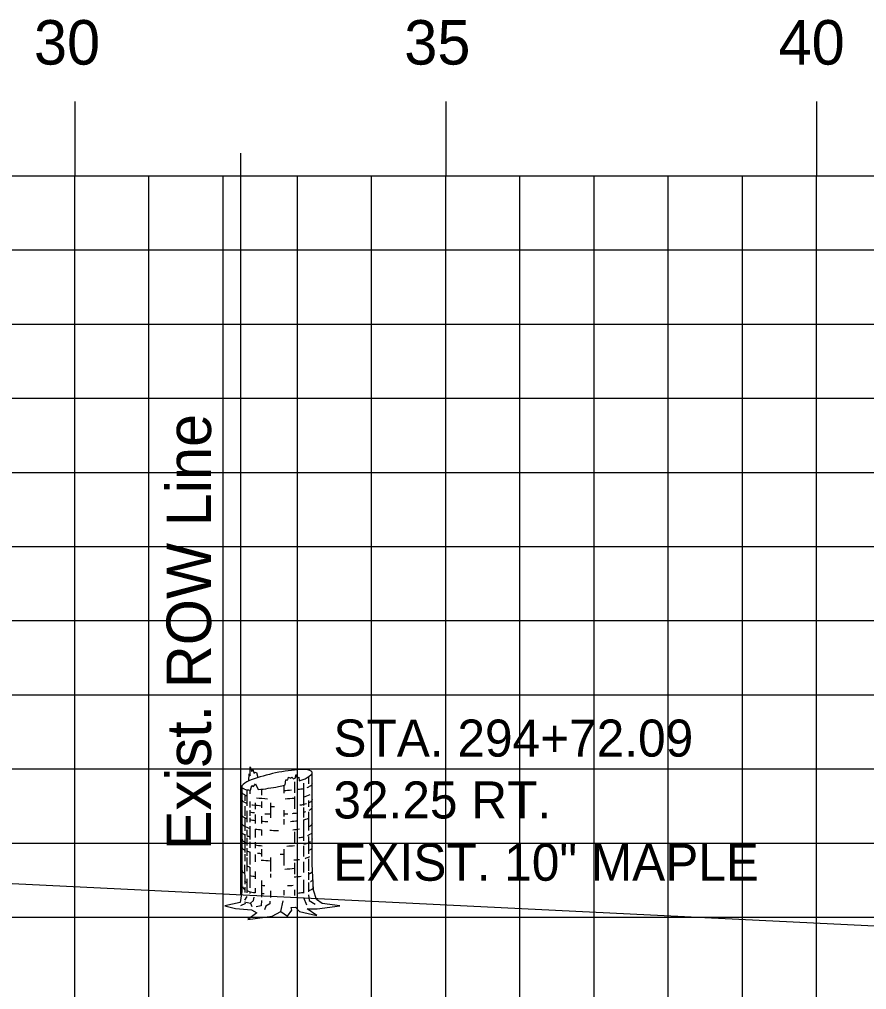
# Model space of a CAD drawing. Extents: x 859352 to 859522, y 366268 to 366378.
# Drawn here: x 859464.38 to 859475.8, y 366316.26 to 366329.35 of the extents above; entities that cross this region are included whole.
import ezdxf

# ---------------------------------------------------------------- set-up
doc = ezdxf.new("R2010")
doc.units = 0
for name, color, linetype in [('D_Text_Monospaced', 7, 'Continuous'), ('E_ROW_Line', 7, 'Continuous'), ('H_V ANNOTATION', 7, 'Continuous'), ('MAJOR', 7, 'Continuous'), ('MINOR', 7, 'Continuous'), ('S_Roadway_Centerline', 7, 'Continuous'), ('S_Trees_Decid_NonPay', 7, 'Continuous')]:
    doc.layers.add(name, color=color, linetype=linetype)

msp = doc.modelspace()

# ---------------------------------------------------------------- linework, layer by layer
at = {"layer": 'E_ROW_Line'}
msp.add_line((859467.365, 366317.54), (859467.365, 366327.54), dxfattribs=at)
at = {"layer": 'MAJOR'}
for p, q in [((859465.129, 366328.238), (859465.129, 366327.236)), ((859470.129, 366328.238), (859470.129, 366327.236)), ((859475.129, 366328.238), (859475.129, 366327.236)), ((859365.129, 366327.236), (859505.129, 366327.236)), ((859365.129, 366327.236), (859505.129, 366327.236)), ((859465.129, 366307.236), (859465.129, 366327.236)), ((859470.129, 366307.236), (859470.129, 366327.236)), ((859475.129, 366307.236), (859475.129, 366327.236)), ((859365.129, 366322.236), (859505.129, 366322.236)), ((859365.129, 366317.236), (859505.129, 366317.236))]:
    msp.add_line(p, q, dxfattribs=at)
at = {"layer": 'MINOR'}
for p, q in [((859466.129, 366307.236), (859466.129, 366327.236)), ((859467.129, 366307.236), (859467.129, 366327.236)), ((859468.129, 366307.236), (859468.129, 366327.236)), ((859469.129, 366307.236), (859469.129, 366327.236)), ((859471.129, 366307.236), (859471.129, 366327.236)), ((859472.129, 366307.236), (859472.129, 366327.236)), ((859473.129, 366307.236), (859473.129, 366327.236)), ((859474.129, 366307.236), (859474.129, 366327.236)), ((859365.129, 366326.236), (859505.129, 366326.236)), ((859365.129, 366325.236), (859505.129, 366325.236)), ((859365.129, 366324.236), (859505.129, 366324.236)), ((859365.129, 366323.236), (859505.129, 366323.236)), ((859365.129, 366321.236), (859505.129, 366321.236)), ((859365.129, 366320.236), (859505.129, 366320.236)), ((859365.129, 366319.236), (859505.129, 366319.236)), ((859365.129, 366318.236), (859505.129, 366318.236))]:
    msp.add_line(p, q, dxfattribs=at)
at = {"layer": 'S_Roadway_Centerline'}
msp.add_lwpolyline([(859412.42, 366318.362), (859414.836, 366318.508), (859414.896, 366318.514), (859415.419, 366318.501), (859418.966, 366318.416), (859419.801, 366318.381), (859419.866, 366318.325), (859420.288, 366317.857), (859421.018, 366317.889), (859421.622, 366317.921), (859424.052, 366318.059), (859425.006, 366318.102), (859426.771, 366318.136), (859435.819, 366318.308), (859444.518, 366318.087), (859445.568, 366318.061), (859451.933, 366317.51), (859452.326, 366317.489), (859453.214, 366317.483), (859453.855, 366318.068), (859453.912, 366318.103), (859458.18, 366317.935), (859464.006, 366317.706), (859478.018, 366317.015)], dxfattribs=at)
at = {"layer": 'S_Trees_Decid_NonPay'}
for p, q in [((859468.092, 366319.061), (859468.092, 366318.912)), ((859468.21, 366319.044), (859468.21, 366318.743)), ((859468.279, 366319.13), (859468.279, 366319.036)), ((859467.447, 366318.957), (859467.447, 366318.739)), ((859467.49, 366318.952), (859467.49, 366318.9)), ((859467.647, 366318.962), (859467.647, 366318.883)), ((859467.945, 366319.015), (859467.945, 366318.908)), ((859467.42, 366318.887), (859467.42, 366318.805)), ((859467.49, 366318.797), (859467.49, 366318.714)), ((859467.561, 366318.778), (859467.561, 366318.692)), ((859467.647, 366318.797), (859467.647, 366318.712)), ((859467.765, 366318.778), (859467.765, 366318.578)), ((859468.092, 366318.864), (859468.092, 366318.696)), ((859468.279, 366318.809), (859468.279, 366318.727)), ((859467.42, 366318.735), (859467.42, 366318.605)), ((859467.447, 366318.67), (859467.447, 366318.519)), ((859467.49, 366318.679), (859467.49, 366318.605)), ((859467.945, 366318.679), (859467.945, 366318.593)), ((859468.21, 366318.714), (859468.21, 366318.583)), ((859468.279, 366318.657), (859468.279, 366318.406)), ((859467.42, 366318.583), (859467.42, 366318.401)), ((859467.49, 366318.578), (859467.49, 366318.519)), ((859467.561, 366318.622), (859467.561, 366318.5)), ((859467.647, 366318.601), (859467.647, 366318.5)), ((859467.945, 366318.558), (859467.945, 366318.488)), ((859468.21, 366318.549), (859468.21, 366318.268)), ((859467.447, 366318.414), (859467.447, 366318.336)), ((859467.49, 366318.465), (859467.49, 366318.284)), ((859467.561, 366318.425), (859467.561, 366318.311)), ((859467.647, 366318.416), (859467.647, 366318.339)), ((859468.092, 366318.389), (859468.092, 366318.241)), ((859467.42, 366318.354), (859467.42, 366318.107)), ((859467.447, 366318.309), (859467.447, 366318.202)), ((859467.49, 366318.253), (859467.49, 366318.171)), ((859467.561, 366318.249), (859467.561, 366318.167)), ((859468.279, 366318.323), (859468.279, 366318.093)), ((859467.447, 366318.167), (859467.447, 366318.066)), ((859467.49, 366318.117), (859467.49, 366317.946)), ((859467.647, 366318.154), (859467.647, 366318.057)), ((859467.945, 366318.154), (859467.945, 366317.932)), ((859468.21, 366318.198), (859468.21, 366318.053)), ((859467.42, 366318.088), (859467.42, 366317.994)), ((859467.447, 366318.04), (859467.447, 366317.858)), ((859467.561, 366318.08), (859467.561, 366317.983)), ((859467.765, 366318.041), (859467.765, 366317.854)), ((859468.279, 366318.023), (859468.279, 366317.862)), ((859467.418, 366317.941), (859467.42, 366317.681)), ((859467.49, 366317.913), (859467.49, 366317.633)), ((859467.561, 366317.854), (859467.561, 366317.755)), ((859468.092, 366317.971), (859468.092, 366317.818)), ((859468.21, 366317.983), (859468.21, 366317.841)), ((859467.447, 366317.755), (859467.447, 366317.563)), ((859467.647, 366317.733), (859467.647, 366317.508)), ((859467.765, 366317.823), (859467.765, 366317.77)), ((859468.21, 366317.74), (859468.21, 366317.559)), ((859468.279, 366317.845), (859468.279, 366317.74)), ((859467.42, 366317.642), (859467.42, 366317.568)), ((859467.561, 366317.626), (859467.561, 366317.567)), ((859467.765, 366317.594), (859467.765, 366317.504)), ((859467.945, 366317.599), (859467.945, 366317.532)), ((859468.092, 366317.607), (859468.092, 366317.528)), ((859468.279, 366317.704), (859468.279, 366317.58)), ((859467.449, 366317.516), (859467.415, 366317.465)), ((859467.49, 366317.581), (859467.49, 366317.555)), ((859468.211, 366317.5), (859468.252, 366317.403)), ((859467.367, 366317.395), (859467.435, 366317.425)), ((859467.905, 366317.313), (859467.939, 366317.458))]:
    msp.add_line(p, q, dxfattribs=at)
for points in [[(859467.379, 366318.994), (859467.379, 366317.582), (859467.357, 366317.434), (859467.153, 366317.391), (859467.293, 366317.355), (859467.512, 366317.337), (859467.581, 366317.294), (859467.46, 366317.205), (859467.791, 366317.248), (859467.905, 366317.313), (859467.997, 366317.252), (859468.053, 366317.331), (859468.044, 366317.368), (859468.106, 366317.37), (859468.158, 366317.313), (859468.39, 366317.261), (859468.263, 366317.349), (859468.395, 366317.351), (859468.703, 366317.389), (859468.464, 366317.42), (859468.386, 366317.477), (859468.348, 366317.599), (859468.331, 366317.952), (859468.331, 366319.186)], [(859467.474, 366319.075), (859467.478, 366319.17), (859467.493, 366319.143), (859467.493, 366319.264), (859467.514, 366319.2), (859467.528, 366319.233), (859467.544, 366319.177), (859467.561, 366319.194), (859467.579, 366319.186), (859467.598, 366319.119)], [(859467.497, 366318.951), (859467.514, 366319.013), (859467.536, 366319.001), (859467.567, 366319.036), (859467.6, 366318.958)], [(859467.966, 366319.02), (859467.975, 366319.087), (859467.999, 366319.091), (859468.008, 366319.126), (859468.039, 366319.112), (859468.053, 366319.126), (859468.077, 366319.103), (859468.1, 366319.112), (859468.113, 366319.161), (859468.121, 366319.118), (859468.151, 366319.126), (859468.155, 366319.075)], [(859467.497, 366317.425), (859467.54, 366317.46), (859467.548, 366317.508)], [(859467.645, 366317.46), (859467.639, 366317.391), (859467.575, 366317.378)], [(859468.281, 366317.537), (859468.29, 366317.46), (859468.368, 366317.411)], [(859467.418, 366317.442), (859467.497, 366317.425), (859467.514, 366317.382)], [(859467.756, 366317.454), (859467.756, 366317.418), (859467.705, 366317.387), (859467.688, 366317.337)]]:
    msp.add_lwpolyline(points, dxfattribs=at)
for centre, radius, start, end in [((859468.35, 366316.728), 2.507, 101.8277, 109.7098), ((859468.35, 366316.728), 2.507, 93.9457, 101.8277), ((859468.199, 366318.908), 0.322, 71.8277, 93.9457), ((859468.27, 366319.125), 0.0935, 60.604, 71.8277), ((859468.249, 366319.226), 0.0935, 311.8277, 323.0514), ((859468.3, 366319.177), 0.0336, 41.8277, 60.604), ((859468.297, 366319.19), 0.0336, 323.0514, 341.8277), ((859468.307, 366319.183), 0.0237, 27.8832, 41.8277), ((859468.312, 366319.186), 0.0179, 11.8277, 27.8832), ((859468.307, 366319.186), 0.0237, 341.8277, 355.7722), ((859468.312, 366319.186), 0.0179, 355.7722, 11.8277), ((859467.613, 366318.785), 0.322, 109.7098, 131.8277), ((859467.36, 366321.453), 2.507, 288.4719, 289.7098), ((859468.097, 366319.396), 0.322, 289.7098, 311.8277), ((859468.306, 366319.04), 0.0252, 330, 343.9485), ((859468.312, 366319.039), 0.0191, 0, 16.0515), ((859468.312, 366319.039), 0.0191, 343.9485, 0), ((859467.403, 366318.994), 0.0237, 161.8277, 175.7722), ((859467.397, 366318.994), 0.0179, 175.7722, 191.8277), ((859467.397, 366318.994), 0.0179, 191.8277, 207.8832), ((859467.399, 366318.925), 0.0191, 173.8872, 180), ((859467.399, 366318.925), 0.0191, 180, 196.0515), ((859467.412, 366318.991), 0.0336, 143.0514, 161.8277), ((859467.402, 366318.997), 0.0237, 207.8832, 221.8277), ((859467.405, 366318.927), 0.0252, 196.0515, 210), ((859467.414, 366318.932), 0.0356, 210, 228.7494), ((859467.41, 366319.004), 0.0336, 221.8277, 240.604), ((859467.46, 366318.955), 0.0935, 131.8277, 143.0514), ((859467.456, 366318.979), 0.0984, 228.7494, 240), ((859467.439, 366319.056), 0.0935, 240.604, 251.8277), ((859467.51, 366319.273), 0.322, 251.8277, 267.5521), ((859467.36, 366321.453), 2.507, 275.4987, 281.8277), ((859467.36, 366321.453), 2.507, 281.8277, 284.0013), ((859467.856, 366321.3), 2.356, 272.1614, 274.76), ((859467.856, 366321.3), 2.356, 276.7201, 278.1032), ((859468.142, 366319.29), 0.326, 278.1032, 282.1964), ((859468.142, 366319.29), 0.326, 291.6757, 300), ((859468.256, 366319.093), 0.0984, 300, 311.2506), ((859468.297, 366319.046), 0.0356, 311.2506, 330), ((859467.399, 366318.824), 0.0191, 173.8872, 180), ((859467.399, 366318.824), 0.0191, 180, 196.0515), ((859467.405, 366318.826), 0.0252, 196.0515, 210), ((859467.414, 366318.831), 0.0356, 210, 228.7494), ((859467.456, 366318.879), 0.0984, 228.7494, 240), ((859467.569, 366319.177), 0.326, 240, 248.0494), ((859467.569, 366319.076), 0.326, 240, 248.0494), ((859467.856, 366321.187), 2.356, 263.2266, 266.8519), ((859467.856, 366321.187), 2.356, 272.6327, 275.758), ((859468.142, 366319.076), 0.326, 278.1032, 289.5833), ((859468.142, 366319.177), 0.326, 282.1964, 299.0901), ((859468.142, 366319.076), 0.326, 296.4281, 300), ((859468.256, 366318.879), 0.0984, 300, 311.2506), ((859468.297, 366318.831), 0.0356, 311.2506, 330), ((859468.306, 366318.826), 0.0252, 330, 343.9485), ((859468.312, 366318.824), 0.0191, 0, 16.0515), ((859468.312, 366318.824), 0.0191, 343.9485, 0), ((859467.399, 366318.722), 0.0191, 173.8872, 180), ((859467.399, 366318.722), 0.0191, 180, 196.0515), ((859467.569, 366318.973), 0.326, 255.9618, 261.8968), ((859467.569, 366319.076), 0.326, 260.9146, 261.8968), ((859467.856, 366321.086), 2.356, 261.8968, 264.9353), ((859467.856, 366320.983), 2.356, 261.8968, 262.6162), ((859467.856, 366321.086), 2.356, 267.8019, 269.1881), ((859467.856, 366320.983), 2.356, 275.0054, 276.6587), ((859467.856, 366321.086), 2.356, 277.4481, 278.1032), ((859468.142, 366318.973), 0.326, 282.1964, 288.3169), ((859468.142, 366318.973), 0.326, 296.757, 300), ((859468.256, 366318.776), 0.0984, 300, 311.2506), ((859468.297, 366318.728), 0.0356, 311.2506, 330), ((859468.306, 366318.723), 0.0252, 330, 343.9485), ((859468.312, 366318.722), 0.0191, 0, 16.0515), ((859468.312, 366318.722), 0.0191, 343.9485, 0), ((859467.399, 366318.617), 0.0191, 173.8872, 180), ((859467.399, 366318.617), 0.0191, 180, 196.0515), ((859467.405, 366318.618), 0.0252, 196.0515, 210), ((859467.414, 366318.623), 0.0356, 210, 228.7494), ((859467.456, 366318.671), 0.0984, 228.7494, 240), ((859467.569, 366318.868), 0.326, 240, 248.0494), ((859467.569, 366318.868), 0.326, 255.9618, 261.8968), ((859467.856, 366320.878), 2.356, 261.8968, 262.8132), ((859467.856, 366320.878), 2.356, 264.9353, 266.9933), ((859467.856, 366320.983), 2.356, 266.0259, 267.8019), ((859467.856, 366320.983), 2.356, 272.1614, 273.4964), ((859467.856, 366320.878), 2.356, 274.3638, 276.7318), ((859468.142, 366318.868), 0.326, 282.1964, 294.8455), ((859467.398, 366318.387), 0.0191, 173.8872, 180), ((859467.398, 366318.387), 0.0191, 180, 196.0515), ((859467.399, 366318.501), 0.0191, 173.8872, 180), ((859467.399, 366318.501), 0.0191, 180, 196.0515), ((859467.404, 366318.389), 0.0252, 196.0515, 210), ((859467.405, 366318.503), 0.0252, 196.0515, 210), ((859467.414, 366318.508), 0.0356, 210, 228.7494), ((859467.413, 366318.394), 0.0356, 210, 228.7494), ((859467.456, 366318.556), 0.0984, 228.7494, 240), ((859467.569, 366318.753), 0.326, 240, 255.9618), ((859467.856, 366320.763), 2.356, 262.8132, 264.9353), ((859467.856, 366320.763), 2.356, 267.586, 270), ((859467.856, 366320.763), 2.356, 270, 270.4422), ((859467.856, 366320.763), 2.356, 275.2089, 277.3412), ((859468.142, 366318.753), 0.326, 294.8455, 300), ((859468.256, 366318.556), 0.0984, 300, 311.2506), ((859468.297, 366318.508), 0.0356, 311.2506, 330), ((859468.296, 366318.394), 0.0356, 311.2506, 330), ((859468.305, 366318.389), 0.0252, 330, 343.9485), ((859468.306, 366318.503), 0.0252, 330, 343.9485), ((859468.312, 366318.501), 0.0191, 0, 16.0515), ((859468.312, 366318.501), 0.0191, 343.9485, 0), ((859468.311, 366318.387), 0.0191, 0, 16.0515), ((859468.311, 366318.387), 0.0191, 343.9485, 0), ((859467.402, 366318.287), 0.0191, 173.8872, 180), ((859467.402, 366318.287), 0.0191, 180, 196.0515), ((859467.407, 366318.288), 0.0252, 196.0515, 210), ((859467.417, 366318.294), 0.0356, 210, 228.7494), ((859467.455, 366318.441), 0.0984, 228.7494, 240), ((859467.458, 366318.341), 0.0984, 228.7494, 240), ((859467.569, 366318.638), 0.326, 240, 242.9942), ((859467.572, 366318.538), 0.326, 240, 247.5951), ((859467.569, 366318.638), 0.326, 248.1902, 256.0964), ((859467.855, 366320.648), 2.356, 277.1385, 278.1032), ((859468.141, 366318.638), 0.326, 278.1032, 282.3301), ((859468.144, 366318.538), 0.326, 283.0921, 300), ((859468.141, 366318.638), 0.326, 292.1344, 300), ((859468.255, 366318.441), 0.0984, 300, 311.2506), ((859468.314, 366318.287), 0.0191, 0, 16.0515), ((859467.399, 366318.182), 0.0191, 173.8872, 180), ((859467.399, 366318.182), 0.0191, 180, 196.0515), ((859467.405, 366318.184), 0.0252, 196.0515, 210), ((859467.414, 366318.189), 0.0356, 210, 228.7494), ((859467.456, 366318.236), 0.0984, 228.7494, 240), ((859467.569, 366318.433), 0.326, 240, 242.8475), ((859467.569, 366318.433), 0.326, 248.0494, 255.9618), ((859467.858, 366320.548), 2.356, 262.7545, 265.0266), ((859467.858, 366320.548), 2.356, 273.1471, 275.6557), ((859468.142, 366318.433), 0.326, 294.8455, 300), ((859468.256, 366318.236), 0.0984, 300, 311.2506), ((859468.297, 366318.189), 0.0356, 311.2506, 330), ((859468.306, 366318.184), 0.0252, 330, 343.9485), ((859468.312, 366318.182), 0.0191, 0, 16.0515), ((859468.312, 366318.182), 0.0191, 343.9485, 0), ((859467.399, 366318.091), 0.0191, 173.8872, 180), ((859467.856, 366320.443), 2.356, 263.572, 264.9353), ((859467.856, 366320.353), 2.356, 264.7274, 267.8019), ((859467.856, 366320.443), 2.356, 270.9946, 272.1614), ((859467.856, 366320.353), 2.356, 275.5135, 277.4157), ((859468.142, 366318.343), 0.326, 286.0817, 298.061), ((859467.403, 366317.863), 0.0191, 173.8872, 180), ((859467.403, 366317.863), 0.0191, 180, 196.0515), ((859467.409, 366317.865), 0.0252, 196.0515, 210), ((859467.569, 366318.23), 0.326, 248.0494, 255.9618), ((859467.856, 366320.24), 2.356, 272.531, 275.758), ((859468.31, 366317.865), 0.0252, 330, 343.9485), ((859468.316, 366317.863), 0.0191, 0, 16.0515), ((859468.316, 366317.863), 0.0191, 343.9485, 0), ((859467.418, 366317.87), 0.0356, 210, 228.7494), ((859467.46, 366317.917), 0.0984, 228.7494, 240), ((859467.573, 366318.114), 0.326, 255.2259, 261.8968), ((859467.86, 366320.124), 2.356, 261.8968, 262.7137), ((859467.86, 366320.124), 2.356, 275.5148, 277.7774), ((859468.146, 366318.114), 0.326, 294.0625, 300), ((859468.26, 366317.917), 0.0984, 300, 311.2506), ((859468.265, 366317.807), 0.0984, 300, 311.2506), ((859468.301, 366317.87), 0.0356, 311.2506, 330), ((859468.306, 366317.759), 0.0356, 311.2506, 330), ((859468.315, 366317.754), 0.0252, 330, 343.9485), ((859468.321, 366317.752), 0.0191, 0, 16.0515), ((859468.321, 366317.752), 0.0191, 343.9485, 0), ((859467.414, 366317.642), 0.0191, 173.8872, 180), ((859467.414, 366317.642), 0.0191, 180, 196.0515), ((859467.42, 366317.644), 0.0252, 196.0515, 210), ((859467.429, 366317.649), 0.0356, 210, 228.7494), ((859467.47, 366317.696), 0.0984, 228.7494, 240), ((859467.578, 366318.004), 0.326, 240, 246.3456), ((859467.584, 366317.893), 0.326, 245.2906, 261.8968), ((859467.864, 366320.014), 2.356, 264.7171, 265.8136), ((859467.864, 366320.014), 2.356, 273.1842, 275.0911), ((859468.156, 366317.893), 0.326, 292.0839, 300), ((859468.151, 366318.004), 0.326, 298.0903, 300), ((859468.27, 366317.696), 0.0984, 300, 311.2506), ((859468.311, 366317.649), 0.0356, 311.2506, 330), ((859468.32, 366317.644), 0.0252, 330, 343.9485), ((859468.326, 366317.642), 0.0191, 0, 16.0515), ((859468.326, 366317.642), 0.0191, 343.9485, 0), ((859467.87, 366319.903), 2.356, 261.8968, 262.4597), ((859467.87, 366319.903), 2.356, 264.5833, 265.4449), ((859467.87, 366319.903), 2.356, 276.4667, 278.1032), ((859468.156, 366317.893), 0.326, 278.1032, 279.6166)]:
    msp.add_arc(centre, radius, start, end, dxfattribs=at)

# ---------------------------------------------------------------- texts
at = {"layer": 'D_Text_Monospaced'}
for s, height, p in [('STA. 294+72.09', 0.49998, (859468.615, 366319.402)), ('32.25 RT.', 0.5, (859468.615, 366318.568)), ('EXIST. 10" MAPLE', 0.49998, (859468.615, 366317.728))]:
    msp.add_text(s, height=height, dxfattribs=at).set_placement(p)
at = {"layer": 'E_ROW_Line'}
msp.add_text('Exist. ROW Line', height=0.6, rotation=90, dxfattribs=at).set_placement((859466.965, 366318.14))
at = {"layer": 'H_V ANNOTATION'}
for s, p in [('30', (859464.578, 366328.736)), ('35', (859469.57, 366328.736)), ('40', (859474.616, 366328.736))]:
    msp.add_text(s, height=0.6, dxfattribs=at).set_placement(p)

doc.saveas('drawing.dxf')
